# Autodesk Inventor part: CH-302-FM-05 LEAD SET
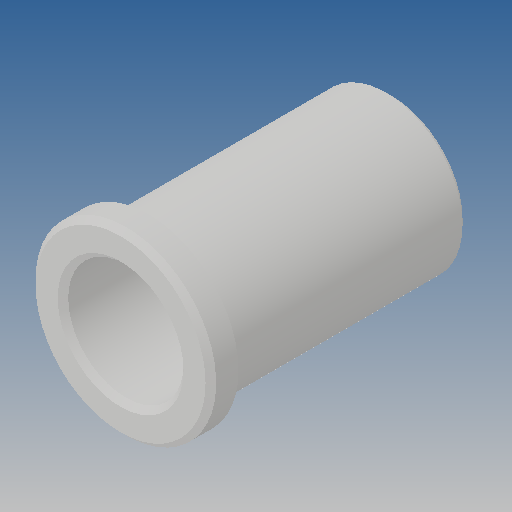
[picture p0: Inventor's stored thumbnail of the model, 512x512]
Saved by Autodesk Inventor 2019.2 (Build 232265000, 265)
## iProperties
Created: 2013-03
Part Number: CH-302-FM-05 LEAD SET
Material: Ogólny
Document SubType Name: Modeling
Designer: CADENGINEERING4
Density: 1 g/cm^3
Appearance: Domyślna
Author: CADENGINEERING4
Revision Number: ÈÎºÎ
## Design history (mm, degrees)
feature "µ¹½Ç2"
node "Bryła1"
